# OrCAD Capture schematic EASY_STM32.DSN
size C; title: EASY_STM32; rev: A
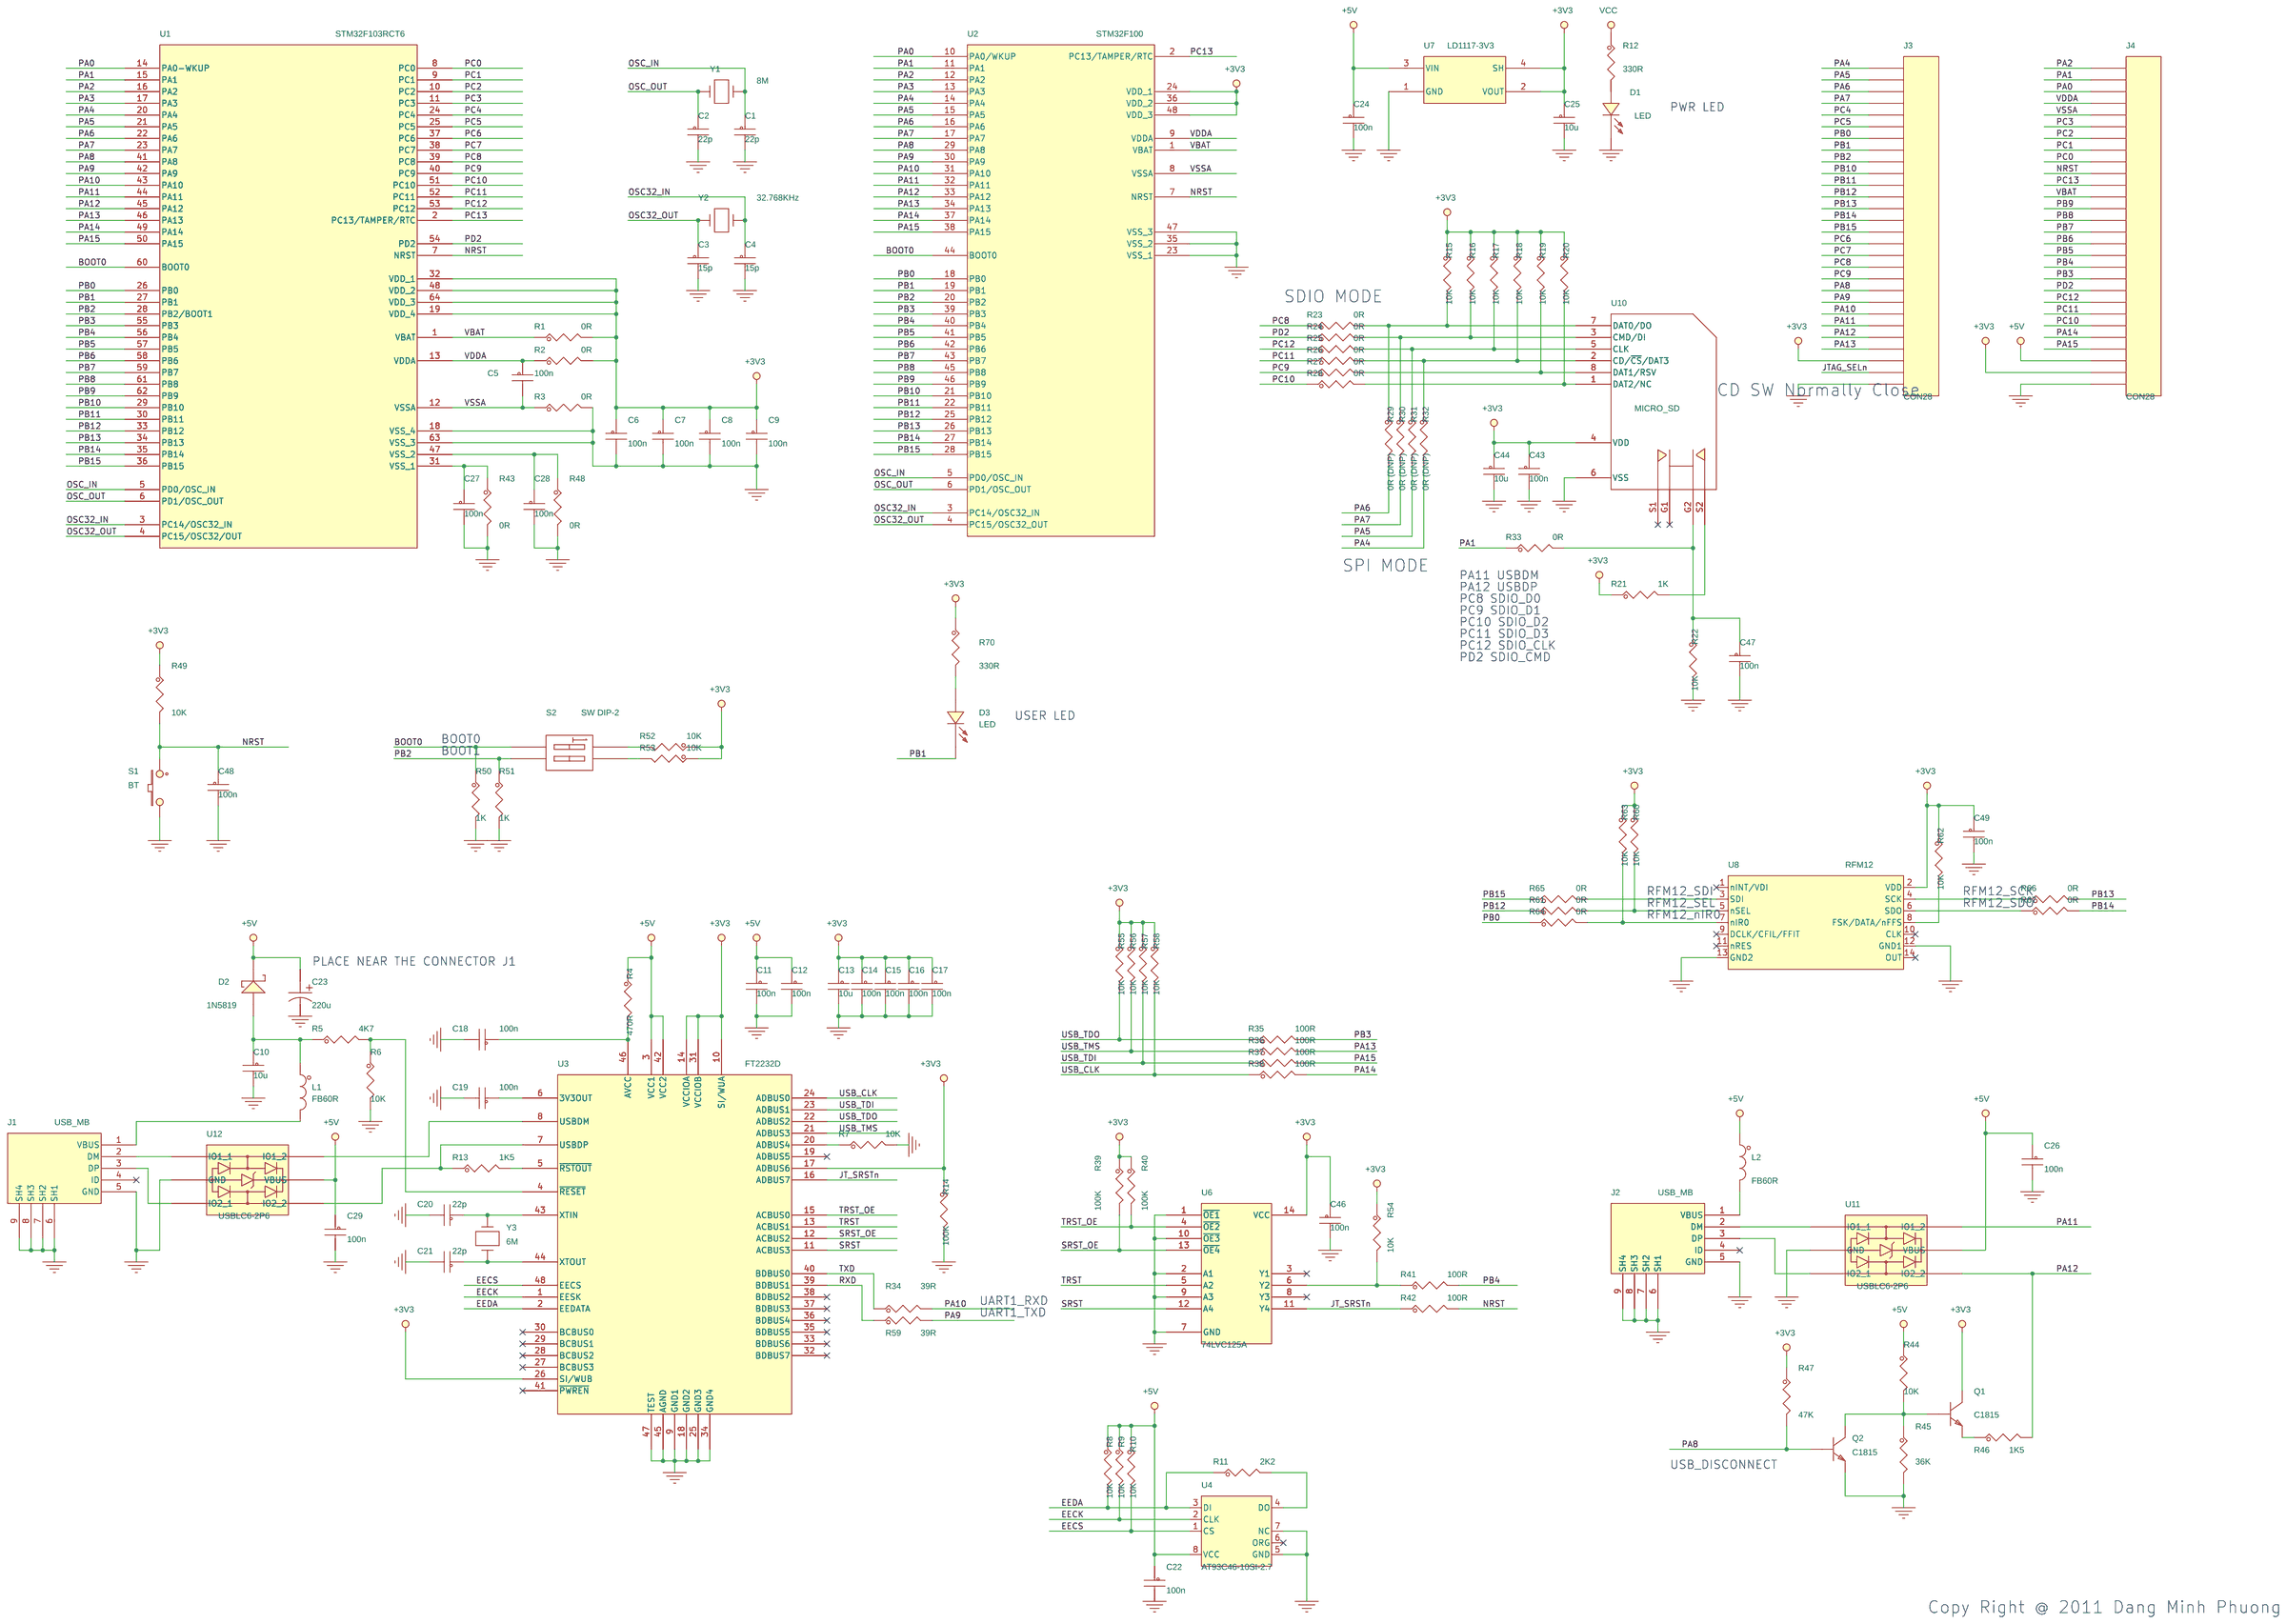
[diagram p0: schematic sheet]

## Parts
C1  22p  [CAP0603_B]
C2  22p  [CAP0603_B]
C3  15p  [CAP0603_B]
C4  15p  [CAP0603_B]
C5  100n  [CAP0603_B]
C6  100n  [CAP0603_B]
C7  100n  [CAP0603_B]
C8  100n  [CAP0603_B]
C9  100n  [CAP0603_B]
C10  10u  [CAP0603_B]
C11  100n  [CAP0603_B]
C12  100n  [CAP0603_B]
C13  10u  [CAP0603_B]
C14  100n  [CAP0603_B]
C15  100n  [CAP0603_B]
C16  100n  [CAP0603_B]
C17  100n  [CAP0603_B]
C18  100n  [CAP0603_B]
C19  100n  [CAP0603_B]
C20  22p  [CAP0603_B]
C21  22p  [CAP0603_B]
C22  100n  [CAP0603_B]
C23  220u  [CAP220UF]
C24  100n  [CAP0603_B]
C25  10u  [CAP0603_B]
C26  100n  [CAP0603_B]
C27  100n  [CAP0603_B]
C28  100n  [CAP0603_B]
C29  100n  [CAP0603_B]
C43  100n  [CAP0603_B]
C44  10u  [CAP0603_B]
C46  100n  [CAP0603_B]
C47  100n  [CAP0603_B]
C48  100n  [CAP0603_B]
C49  100n  [CAP0603_B]
D1  LED  [LEDC2012X120M]
D2  1N5819  [SS14]
D3  LED  [LEDC2012X120M]
J1  USB_MB  [HIROSE-US60-MB-5ST]
J2  USB_MB  [HIROSE-US60-MB-5ST]
J3  CON28  [CON28-1X28]
J4  CON28  [CON28-1X28]
L1  FB60R  [RES0805_B]
L2  FB60R  [RES0805_B]
Q1  C1815  [SOT-23]
Q2  C1815  [SOT-23]
R1  0R  [RES0603_B]
R2  0R  [RES0603_B]
R3  0R  [RES0603_B]
R4  470R  [RES0603_B]
R5  4K7  [RES0603_B]
R6  10K  [RES0603_B]
R7  10K  [RES0603_B]
R8  10K  [RES0603_B]
R9  10K  [RES0603_B]
R10  10K  [RES0603_B]
R11  2K2  [RES0603_B]
R12  330R  [RES0603_B]
R13  1K5  [RES0603_B]
R14  100K  [RES0603_B]
R15  10K  [RES0603_B]
R16  10K  [RES0603_B]
R17  10K  [RES0603_B]
R18  10K  [RES0603_B]
R19  10K  [RES0603_B]
R20  10K  [RES0603_B]
R21  1K  [RES0603_B]
R22  10K  [RES0603_B]
R23  0R  [RES0603_B]
R24  0R  [RES0603_B]
R25  0R  [RES0603_B]
R26  0R  [RES0603_B]
R27  0R  [RES0603_B]
R28  0R  [RES0603_B]
R29  0R (DNP)  [RES0603_B]
R30  0R (DNP)  [RES0603_B]
R31  0R (DNP)  [RES0603_B]
R32  0R (DNP)  [RES0603_B]
R33  0R  [RES0603_B]
R34  39R  [RES0603_B]
R35  100R  [RES0603_B]
R36  100R  [RES0603_B]
R37  100R  [RES0603_B]
R38  100R  [RES0603_B]
R39  100K  [RES0603_B]
R40  100K  [RES0603_B]
R41  100R  [RES0603_B]
R42  100R  [RES0603_B]
R43  0R  [RES0603_B]
R44  10K  [RES0603_B]
R45  36K  [RES0603_B]
R46  1K5  [RES0603_B]
R47  47K  [RES0603_B]
R48  0R  [RES0603_B]
R49  10K  [RES0603_B]
R50  1K  [RES0603_B]
R51  1K  [RES0603_B]
R52  10K  [RES0603_B]
R53  10K  [RES0603_B]
R54  10K  [RES0603_B]
R55  10K  [RES0603_B]
R56  10K  [RES0603_B]
R57  10K  [RES0603_B]
R58  10K  [RES0603_B]
R59  39R  [RES0603_B]
R60  10K  [RES0603_B]
R61  0R  [RES0603_B]
R62  10K  [RES0603_B]
R63  10K  [RES0603_B]
R64  0R  [RES0603_B]
R65  0R  [RES0603_B]
R66  0R  [RES0603_B]
R67  0R  [RES0603_B]
R70  330R  [RES0603_B]
S1  BT  [BUTTON_RST_CIRCLE]
S2  SW DIP-2  [DIP_SWITCH_2]
U1  STM32F103RCT6  [LQFP64_MODIFIED]
U2  STM32F100  [LQFP48L_MODIFIED]
U3  FT2232D  [LQFP48L]
U4  AT93C46-10SI-2.7  [SOIC8S1JEDECM]
U6  74LVC125A  [TSOP65P640X120-14]
U7  LD1117-3V3  [SOT-223]
U8  RFM12  [RFM12-2X6]
U10  MICRO_SD  [MICRO_SD_PUSH]
U11  USBLC6-2P6  [SOT23-6L]
U12  USBLC6-2P6  [SOT23-6L]
Y1  8M  [XTAL_DIP]
Y2  32.768KHz  [ABS10]
Y3  6M  [XTAL_DIP]

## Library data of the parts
C1-C9 C24 C25 C27 C28 = C1005_0
C10-C22 C26 C29 = CAP_NP_0
C23 = CAPACITOR_POL
C43 C44 C46-C49 = C1005_5
D1 D3 = LED_0
D2 = DIODE_SCHOTTKY_1: Rating: 1 Amp; Type: Schottky
J1 J2 = CON9_2
J3 J4 = CON26_0
L1 L2 = INDUCTOR_SM_0
Q1 Q2 = 2N3904_0
R1-R67 R70 = R_0
S1 = SW_PUSHBUTTON_1
S2 = SW_DIP-2_1
U1 = STM32F103RCT6_2
U2 = STM32F100_1
U3 = FT2232D_0
U4 = 93C46_2
U6 = 74HC125_LCC_0
U7 = LD1117
U8 = RFM12
U10 = MOLEX_uSD_0
U11 U12 = USBLC6-2P6
Y1 Y3 = ZTB
Y2 = ZTA

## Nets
+3V3: C6.1 C7.1 C8.1 C9.1 C13.1 C14.1 C15.1 C16.1 C17.1 C25.1 C43.1 C44.1 C46.1 C49.1 J3.26 J4.27 Q1.3(C) R1.2 R2.2 R12.1 R14.1 R15.1 R16.1 R17.1 R18.1 R19.1 R20.1 R21.1 R39.1 R40.1 R47.1 R49.1 R52.1 R53.1 R54.1 R55.1 R56.1 R57.1 R58.1 R60.1 R62.1 R63.1 R70.1 U1.19(VDD_4) U1.32(VDD_1) U1.48(VDD_2) U1.64(VDD_3) U2.24(VDD_1) U2.36(VDD_2) U2.48(VDD_3) U3.10(SI/WUA) U3.14(VCCIOA) U3.17(ADBUS6) U3.26(SI/WUB) U3.31(VCCIOB) U6.14(VCC) U7.2(VOUT) U7.4(SH) U8.2(VDD) U10.4(VDD)
+5V: C11.1 C12.1 C22.1 C23.1 C24.1 C26.1 C29.1 D2.C J4.26 L2.1 R4.1 R8.1 R9.1 R10.1 R44.1 U3.3(VCC1) U3.42(VCC2) U4.8(VCC) U7.3(VIN) U11.5(VBUS) U12.5(VBUS)
GND: C1.2 C2.2 C3.2 C4.2 C6.2 C7.2 C8.2 C9.2 C10.2 C11.2 C12.2 C13.2 C14.2 C15.2 C16.2 C17.2 C18.2 C19.2 C20.2 C21.2 C22.2 C23.2 C24.2 C25.2 C26.2 C27.2 C28.2 C29.2 C43.2 C44.2 C46.2 C47.2 C48.2 C49.2 D1.C J1.5(GND) J1.6(SH1) J1.7(SH2) J1.8(SH3) J1.9(SH4) J2.5(GND) J2.6(SH1) J2.7(SH2) J2.8(SH3) J2.9(SH4) J3.28 J4.28 Q2.2(E) R3.2 R6.2 R7.2 R14.2 R22.2 R43.2 R45.2 R48.2 R50.2 R51.2 S1.2 U1.18(VSS_4) U1.63(VSS_3) U2.23(VSS_1) U2.35(VSS_2) U2.47(VSS_3) U3.9(GND1) U3.18(GND2) U3.25(GND3) U3.34(GND4) U3.45(AGND) U3.47(TEST) U4.5(GND) U4.7(NC) U6.1(~{OE1}) U6.2(A1) U6.7(GND) U6.9(A3) U6.10(~{OE3}) U7.1(GND) U8.12(GND1) U8.13(GND2) U10.6(VSS) U11.2(GND) U12.2(GND)
VBAT: J4.12 R1.1 U1.1(VBAT) U2.1(VBAT)
VDDA: C5.1 J4.4 R2.1 U1.13(VDDA) U2.9(VDDA)
VSSA: C5.2 J4.5 R3.1 U1.12(VSSA) U2.8(VSSA)
BOOT0: R50.1 S2.1 U1.60(BOOT0) U2.44(BOOT0)
EECK: R9.2 U3.1(EESK) U4.2(CLK)
EECS: R10.2 U3.48(EECS) U4.1(CS)
EEDA: R8.2 R11.1 U3.2(EEDATA) U4.3(DI)
JT_SRSTn: R42.1 U3.16(ADBUS7) U6.11(Y4)
JTAG_SELn: J3.27
NRST: C48.1 J4.10 R42.2 R49.2 S1.1 U1.7(NRST) U2.7(NRST)
OSC32_IN: C4.1 U1.3(PC14/OSC32_IN) U2.3(PC14/OSC32_IN) Y2.1
OSC32_OUT: C3.1 U1.4(PC15/OSC32/OUT) U2.4(PC15/OSC32_OUT) Y2.2
OSC_IN: C1.1 U1.5(PD0/OSC_IN) U2.5(PD0/OSC_IN) Y1.2
OSC_OUT: C2.1 U1.6(PD1/OSC_OUT) U2.6(PD1/OSC_OUT) Y1.1
PA0: J4.3 U1.14(PA0-WKUP) U2.10(PA0/WKUP)
PA1: J4.2 R33.1 U1.15(PA1) U2.11(PA1)
PA2: J4.1 U1.16(PA2) U2.12(PA2)
PA3: U1.17(PA3) U2.13(PA3)
PA4: J3.1 R32.2 U1.20(PA4) U2.14(PA4)
PA5: J3.2 R31.2 U1.21(PA5) U2.15(PA5)
PA6: J3.3 R29.2 U1.22(PA6) U2.16(PA6)
PA7: J3.4 R30.2 U1.23(PA7) U2.17(PA7)
PA8: J3.20 Q2.1(B) R47.2 U1.41(PA8) U2.29(PA8)
PA9: J3.21 R59.2 U1.42(PA9) U2.30(PA9)
PA10: J3.22 R34.2 U1.43(PA10) U2.31(PA10)
PA11: J3.23 U1.44(PA11) U2.32(PA11) U11.6(IO1_2)
PA12: J3.24 R46.2 U1.45(PA12) U2.33(PA12) U11.4(IO2_2)
PA13: J3.25 R36.2 U1.46(PA13) U2.34(PA13)
PA14: J4.24 R38.2 U1.49(PA14) U2.37(PA14)
PA15: J4.25 R37.2 U1.50(PA15) U2.38(PA15)
PB0: J3.7 R64.1 U1.26(PB0) U2.18(PB0)
PB1: D3.C J3.8 U1.27(PB1) U2.19(PB1)
PB2: J3.9 R51.1 S2.2 U1.28(PB2/BOOT1) U2.20(PB2)
PB3: J4.19 R35.2 U1.55(PB3) U2.39(PB3)
PB4: J4.18 R41.2 U1.56(PB4) U2.40(PB4)
PB5: J4.17 U1.57(PB5) U2.41(PB5)
PB6: J4.16 U1.58(PB6) U2.42(PB6)
PB7: J4.15 U1.59(PB7) U2.43(PB7)
PB8: J4.14 U1.61(PB8) U2.45(PB8)
PB9: J4.13 U1.62(PB9) U2.46(PB9)
PB10: J3.10 U1.29(PB10) U2.21(PB10)
PB11: J3.11 U1.30(PB11) U2.22(PB11)
PB12: J3.12 R61.1 U1.33(PB12) U2.25(PB12)
PB13: J3.13 R66.2 U1.34(PB13) U2.26(PB13)
PB14: J3.14 R67.2 U1.35(PB14) U2.27(PB14)
PB15: J3.15 R65.1 U1.36(PB15) U2.28(PB15)
PC0: J4.9 U1.8(PC0)
PC1: J4.8 U1.9(PC1)
PC2: J4.7 U1.10(PC2)
PC3: J4.6 U1.11(PC3)
PC4: J3.5 U1.24(PC4)
PC5: J3.6 U1.25(PC5)
PC6: J3.16 U1.37(PC6)
PC7: J3.17 U1.38(PC7)
PC8: J3.18 R23.1 U1.39(PC8)
PC9: J3.19 R27.1 U1.40(PC9)
PC10: J4.23 R28.1 U1.51(PC10)
PC11: J4.22 R26.1 U1.52(PC11)
PC12: J4.21 R25.1 U1.53(PC12)
PC13: J4.11 U1.2(PC13/TAMPER/RTC) U2.2(PC13/TAMPER/RTC)
PD2: J4.20 R24.1 U1.54(PD2)
RXD: R59.1 U3.39(BDBUS1)
SRST: U3.11(ACBUS3) U6.12(A4)
SRST_OE: R39.2 U3.12(ACBUS2) U6.13(~{OE4})
TRST: U3.13(ACBUS1) U6.5(A2)
TRST_OE: R40.2 U3.15(ACBUS0) U6.4(~{OE2})
TXD: R34.1 U3.40(BDBUS0)
USB_CLK: R38.1 R58.2 U3.24(ADBUS0)
USB_TDI: R37.1 R57.2 U3.23(ADBUS1)
USB_TDO: R35.1 R55.2 U3.22(ADBUS2)
USB_TMS: R36.1 R56.2 U3.21(ADBUS3)
N50123: R13.1 U3.7(USBDP) U12.4(IO2_2)
N50127: C18.1 R4.2 U3.46(AVCC)
N50535: R7.1 U3.20(ADBUS4)
N50793: C20.1 U3.43(XTIN) Y3.1
N50801: C21.1 U3.44(XTOUT) Y3.2
N51029: C10.1 D2.A L1.1 R5.1
N51243: J1.1(VBUS) L1.2
N51319: R13.2 U3.5(~{RSTOUT})
N51343: U3.8(USBDM) U12.6(IO1_2)
N51347: R5.2 R6.1 U3.4(~{RESET})
N51363: C19.1 U3.6(3V3OUT)
N51511: R11.2 U4.4(DO)
N51727: D1.A R12.2
N70187: R15.2 R23.2 R29.1 U10.7(DAT0/DO)
N70219: R17.2 R25.2 R31.1 U10.5(CLK)
N70227: R18.2 R26.2 R32.1 U10.2(CD/~{CS}/DAT3)
N70305: R21.2 U10.S2
N70345: C47.1 R22.1 R33.2 U10.G2
N70603: R19.2 R27.2 U10.8(DAT1/RSV)
N14914218: R16.2 R24.2 R30.1 U10.3(CMD/DI)
N14919761: R20.2 R28.2 U10.1(DAT2/NC)
N14928576: R41.1 R54.2 U6.6(Y2)
N14948550: J2.1(VBUS) L2.2
N14948554: J2.2(DM) U11.1(IO1)
N14948558: J2.3(DP) U11.3(IO2_1)
N14952468: Q1.2(E) R46.1
N14953185: Q1.1(B) Q2.3(C) R44.2 R45.1
N14959571: J1.3(DP) U12.3(IO2_1)
N14961045: J1.2(DM) U12.1(IO1)
N14964930: C27.1 R43.1 U1.31(VSS_1)
N14964937: C28.1 R48.1 U1.47(VSS_2)
N14983071: R52.2 S2.4
N14983075: R53.2 S2.3
N14990127: R62.2 U8.8(FSK/DATA/nFFS)
N14990147: R66.1 U8.4(SCK)
N14990153: R67.1 U8.6(SDO)
N14990191: R65.2 U8.3(SDI)
N14990197: R60.2 R61.2 U8.5(nSEL)
N14990201: R63.2 R64.2 U8.7(nIR0)
N15001570: D3.A R70.2

Not connected (* = marked no-connect by the designer): J1 4(ID)*; J2 4(ID)*; U3 19(ADBUS5)* 27(BCBUS3)* 28(BCBUS2)* 29(BCBUS1)* 30(BCBUS0)* 32(BDBUS7)* 33(BDBUS6)* 35(BDBUS5)* 36(BDBUS4)* 37(BDBUS3)* 38(BDBUS2)* 41(~{PWREN})*; U4 6(ORG)*; U6 3(Y1)* 8(Y3)*; U8 1(nINT/VDI)* 9(DCLK/CFIL/FFIT)* 10(CLK)* 11(nRES)* 14(OUT)*; U10 G1* S1*

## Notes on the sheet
- PWR LED
- SDIO MODE
- CD SW Normally Close
- SPI MODE
- PA11 USBDM
- PA12 USBDP
- PC8 SDIO_D0
- PC9 SDIO_D1
- PC10 SDIO_D2
- PC11 SDIO_D3
- PC12 SDIO_CLK
- PD2 SDIO_CMD
- USER LED
- BOOT0
- BOOT1
- RFM12_SDI
- RFM12_SEL
- RFM12_SCK
- RFM12_SDO
- RFM12_nIR0
- PLACE NEAR THE CONNECTOR J1
- UART1_RXD
- UART1_TXD
- USB_DISCONNECT
- Copy Right @ 2011 Dang Minh Phuong
